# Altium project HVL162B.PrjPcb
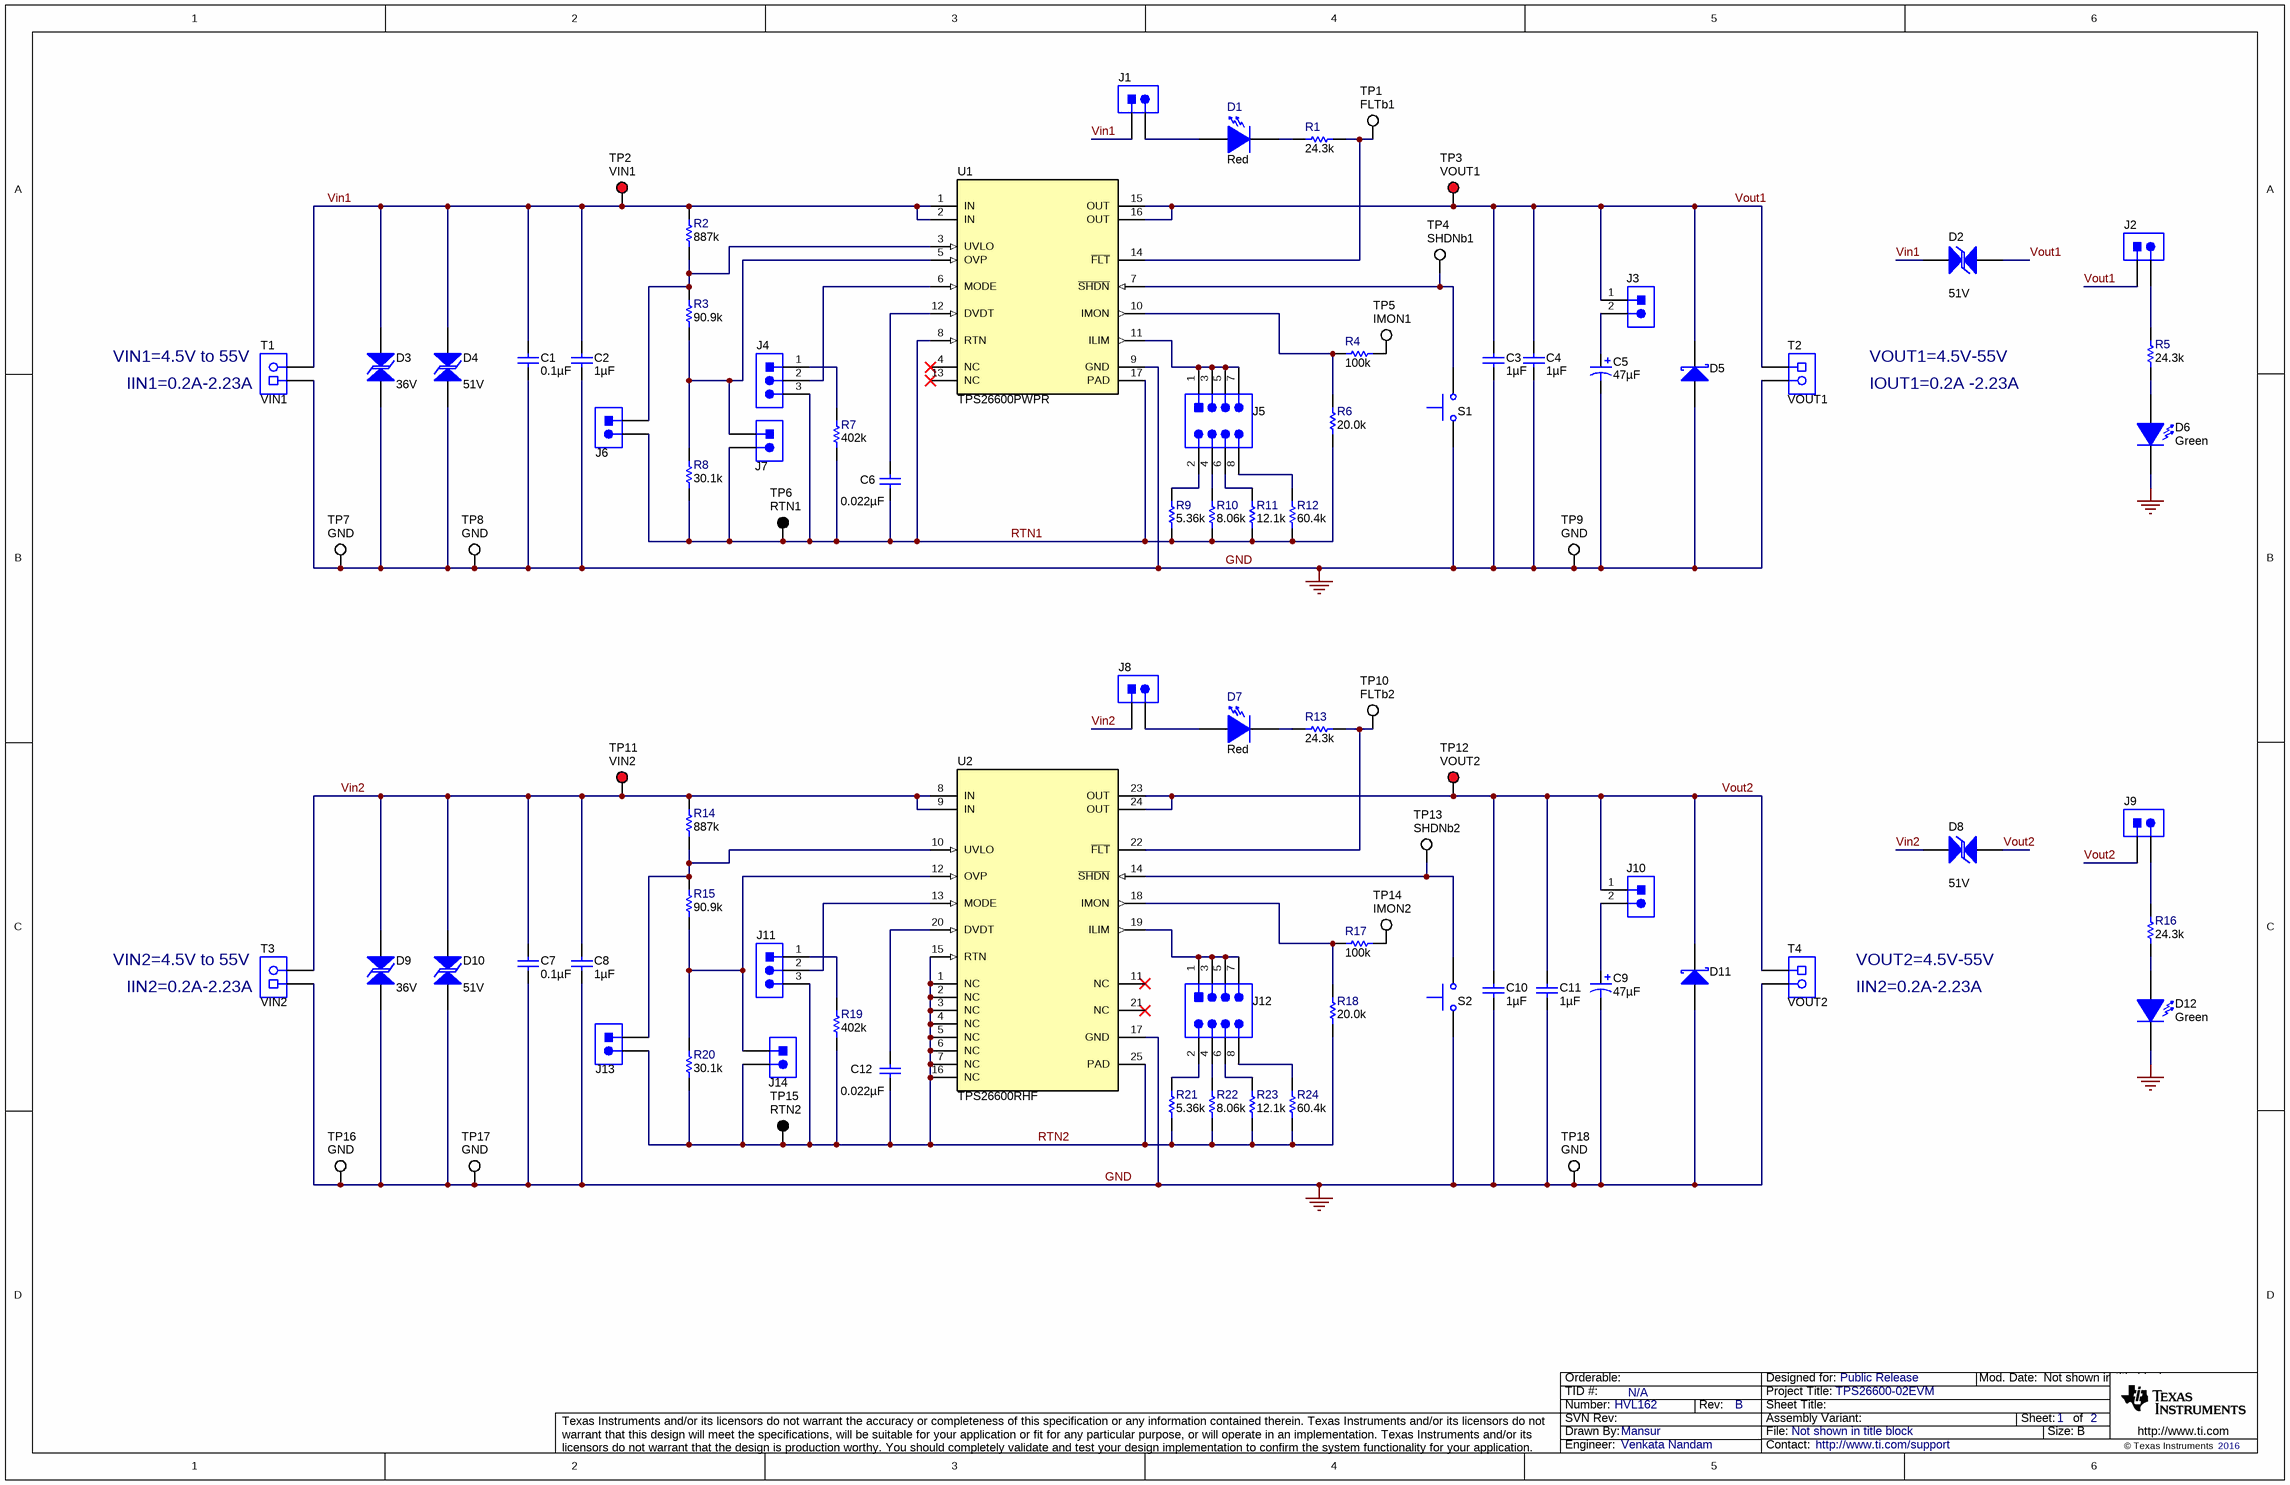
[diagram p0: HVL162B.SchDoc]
TID: N/A; TechSupport: http://www.ti.com/support; SCH_Rev: B; PRJ_Title: TPS26600-02EVM; PRJ_Number: HVL162; PRJ_Engineer: Venkata Nandam; PRJ_Customer: Public Release; PCB_Rev: B; PCB_Layout: Mansur; CopyrightYear: 2016
2 sheets, 116 parts. Net scope: global (net labels, ports and power ports of the same name join across sheets).
Board file: HVL162B.PcbDoc
Sheets:
  HVL162B.SchDoc
  HVL162B_Hardware.SchDoc

## Sheet HVL162B.SchDoc
size 431 x 279 mm; Date: Not shown in title block; ApprovedBy: Not shown in title block; CheckedBy: Not shown in title block; Author: Not shown in title block; CompanyName: Not shown in title block; DrawnBy: Mansur; Engineer: Not shown in title block; Organization: Not shown in title block; Address1: Not shown in title block; Address2: Not shown in title block; Address3: Not shown in title block; Address4: Not shown in title block; DocumentNumber: 1; Revision: Use project parameter SCH_Rev; SheetNumber: 1; SheetTotal: 2; PageSetup: Record=PageOptions¦CenterHorizontal=True¦CenterVertical=True¦PrintScale=0.62¦XCorrection=1.00¦YCorrection=1.00¦PrintKind=0¦BorderSize=5000000¦LeftOffset=0¦BottomOffset=0¦Orientation=2¦PaperLength=1000¦PaperWidth=1000¦Scale=100¦PaperSource=15¦PrintQuality=600¦MediaType=1¦DitherType=10¦PrintScaleMode=1¦PaperKind=Letter

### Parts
C1  ValueDisplayed: 0.1µF  [1206]  (hidden comment: GRM319R72A104KA01D)
C2  ValueDisplayed: 1µF  [1206_180M]  (hidden comment: GRM31CR72A105KA01L)
C3  ValueDisplayed: 1µF  [1206_180M]  (hidden comment: GRM31CR72A105KA01L)
C4  ValueDisplayed: 1µF  [1206_180M]  (hidden comment: GRM31CR72A105KA01L)
C5  ValueDisplayed: 47µF  [SM_RADIAL_G]  (hidden comment: EEETG1J470P)
C6  ValueDisplayed: 0.022µF  [0603]  (hidden comment: GRM188R71C223KA01D)
C7  ValueDisplayed: 0.1µF  [1206]  (hidden comment: GRM319R72A104KA01D)
C8  ValueDisplayed: 1µF  [1206_180M]  (hidden comment: GRM31CR72A105KA01L)
C9  ValueDisplayed: 47µF  [SM_RADIAL_G]  (hidden comment: EEETG1J470P)
C10  ValueDisplayed: 1µF  [1206_180M]  (hidden comment: GRM31CR72A105KA01L)
C11  ValueDisplayed: 1µF  [1206_180M]  (hidden comment: GRM31CR72A105KA01L)
C12  ValueDisplayed: 0.022µF  [0603]  (hidden comment: GRM188R71C223KA01D)
D1  value Red  [LED_LTST-C190_Red]  (hidden comment: LTST-C190CKT)
D2  value 51V  [SMA]  (hidden comment: SMAJ51CA)
D3  value 36V  [SMC]
D4  value 51V  [SMB-Bi]  (hidden comment: SMBJ51CA)
D5  B260A-13-F  [SMA]  (value not drawn)
D6  value Green  [LED_LTST-C190]  (hidden comment: LTST-C190GKT)
D7  value Red  [LED_LTST-C190_Red]  (hidden comment: LTST-C190CKT)
D8  value 51V  [SMA]  (hidden comment: SMAJ51CA)
D9  value 36V  [SMC]
D10  value 51V  [SMB-Bi]  (hidden comment: SMBJ51CA)
D11  B260A-13-F  [SMA]  (value not drawn)
D12  value Green  [LED_LTST-C190]  (hidden comment: LTST-C190GKT)
J1  PBC02SAAN  [Sullins_PBC02SAAN]  (value not drawn)
J2  PBC02SAAN  [Sullins_PBC02SAAN]  (value not drawn)
J3  PBC02SAAN  [Sullins_PBC02SAAN]  (value not drawn)
J4  (no value)  [CONN_PEC03SAAN]
J5  PEC04DAAN  [CONN_PEC04DAAN]  (value not drawn)
J6  PBC02SAAN  [Sullins_PBC02SAAN]  (value not drawn)
J7  PBC02SAAN  [Sullins_PBC02SAAN]  (value not drawn)
J8  PBC02SAAN  [Sullins_PBC02SAAN]  (value not drawn)
J9  PBC02SAAN  [Sullins_PBC02SAAN]  (value not drawn)
J10  PBC02SAAN  [Sullins_PBC02SAAN]  (value not drawn)
J11  (no value)  [CONN_PEC03SAAN]
J12  PEC04DAAN  [CONN_PEC04DAAN]  (value not drawn)
J13  PBC02SAAN  [Sullins_PBC02SAAN]  (value not drawn)
J14  PBC02SAAN  [Sullins_PBC02SAAN]  (value not drawn)
R1  ValueDisplayed: 24.3k  [0603]  (hidden comment: CRCW060324K3FKEA)
R2  ValueDisplayed: 887k  [0603_HV]  (hidden comment: CRCW0603887KFKEA)
R3  ValueDisplayed: 90.9k  [0603_HV]  (hidden comment: CRCW060390K9FKEA)
R4  ValueDisplayed: 100k  [0603]  (hidden comment: CRCW0603100KFKEA)
R5  ValueDisplayed: 24.3k  [0603]  (hidden comment: CRCW060324K3FKEA)
R6  ValueDisplayed: 20.0k  [0603]  (hidden comment: CRCW060320K0FKEA)
R7  ValueDisplayed: 402k  [0603_HV]  (hidden comment: CRCW0603402KFKEA)
R8  ValueDisplayed: 30.1k  [0603_HV]  (hidden comment: CRCW060330K1FKEA)
R9  ValueDisplayed: 5.36k  [0603]  (hidden comment: CRCW06035K36FKEA)
R10  ValueDisplayed: 8.06k  [0603]  (hidden comment: CRCW06038K06FKEA)
R11  ValueDisplayed: 12.1k  [0603]  (hidden comment: CRCW060312K1FKEA)
R12  ValueDisplayed: 60.4k  [0603]  (hidden comment: CRCW060360K4FKEA)
R13  ValueDisplayed: 24.3k  [0603_HV]  (hidden comment: CRCW060324K3FKEA)
R14  ValueDisplayed: 887k  [0603_HV]  (hidden comment: CRCW0603887KFKEA)
R15  ValueDisplayed: 90.9k  [0603_HV]  (hidden comment: CRCW060390K9FKEA)
R16  ValueDisplayed: 24.3k  [0603]  (hidden comment: CRCW060324K3FKEA)
R17  ValueDisplayed: 100k  [0603]  (hidden comment: CRCW0603100KFKEA)
R18  ValueDisplayed: 20.0k  [0603]  (hidden comment: CRCW060320K0FKEA)
R19  ValueDisplayed: 402k  [0603_HV]  (hidden comment: CRCW0603402KFKEA)
R20  ValueDisplayed: 30.1k  [0603_HV]  (hidden comment: CRCW060330K1FKEA)
R21  ValueDisplayed: 5.36k  [0603]  (hidden comment: CRCW06035K36FKEA)
R22  ValueDisplayed: 8.06k  [0603]  (hidden comment: CRCW06038K06FKEA)
R23  ValueDisplayed: 12.1k  [0603]  (hidden comment: CRCW060312K1FKEA)
R24  ValueDisplayed: 60.4k  [0603]  (hidden comment: CRCW060360K4FKEA)
S1  RES-2  [SW_SKRKAEE010]  (value not drawn)
S2  RES-2  [SW_SKRKAEE010]  (value not drawn)
T1  VIN1  [TEC_282841-2]
T2  VOUT1  [TEC_282841-2]
T3  VIN2  [TEC_282841-2]
T4  VOUT2  [TEC_282841-2]
TP1  FLTb1  [Keystone5012]
TP2  VIN1  [Keystone5010]
TP3  VOUT1  [Keystone5010]
TP4  SHDNb1  [Keystone5012]
TP5  IMON1  [Keystone5012]
TP6  RTN1  [Keystone5011]
TP7  GND  [Testpoint_Keystone_Compact]
TP8  GND  [Testpoint_Keystone_Compact]
TP9  GND  [Testpoint_Keystone_Compact]
TP10  FLTb2  [Keystone5012]
TP11  VIN2  [Keystone5010]
TP12  VOUT2  [Keystone5010]
TP13  SHDNb2  [Keystone5012]
TP14  IMON2  [Keystone5012]
TP15  RTN2  [Keystone5011]
TP16  GND  [Testpoint_Keystone_Compact]
TP17  GND  [Testpoint_Keystone_Compact]
TP18  GND  [Testpoint_Keystone_Compact]
U1  PartNumber: TPS26600PWPR  [PWP0016H_N]  (hidden comment: CMP-0074228-2)
U2  TPS26600RHF  [RHF0024A]

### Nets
GND: C1.2 C2.1 C3.2 C4.2 C5.2(-) C7.2 C8.1 C9.2(-) C10.2 C11.2 D3.1 D4.1 D5.2(A) D6.2(K) D9.1 D10.1 D11.2(A) D12.2(K) S1.1 S2.1 T1.1 T2.2 T3.1 T4.2 TP7.1 TP8.1 TP9.1 TP16.1 TP17.1 TP18.1 U1.9(GND) U2.17(GND)
RTN1: C6.2 J4.3 J6.2 J7.2 R6.1 R7.1 R8.1 R9.1 R10.1 R11.1 R12.1 TP6.1 U1.8(RTN) U1.17(PAD)
RTN2: C12.2 J11.3 J13.2 J14.2 R18.1 R19.1 R20.1 R21.1 R22.1 R23.1 R24.1 TP15.1 U2.1(NC) U2.2(NC) U2.3(NC) U2.4(NC) U2.5(NC) U2.6(NC) U2.7(NC) U2.15(RTN) U2.16(NC) U2.25(PAD)
Vin1: C1.1 C2.2 D2.2 D3.2 D4.2 J1.1 R2.2 T1.2 TP2.1 U1.1(IN) U1.2(IN)
Vin2: C7.1 C8.2 D8.2 D9.2 D10.2 J8.1 R14.2 T3.2 TP11.1 U2.8(IN) U2.9(IN)
Vout1: C3.1 C4.1 D2.1 D5.1(K) J2.1 J3.1 T2.1 TP3.1 U1.15(OUT) U1.16(OUT)
Vout2: C10.1 C11.1 D8.1 D11.1(K) J9.1 J10.1 T4.1 TP12.1 U2.23(OUT) U2.24(OUT)
NetC5_1: C5.1(+) J3.2
NetC6_1: C6.1 U1.12(DVDT)
NetC9_1: C9.1(+) J10.2
NetC12_1: C12.1 U2.20(DVDT)
NetD1_1: D1.1(A) J1.2
NetD1_2: D1.2(K) R1.2
NetD6_1: D6.1(A) R5.1
NetD7_1: D7.1(A) J8.2
NetD7_2: D7.2(K) R13.2
NetD12_1: D12.1(A) R16.1
NetJ2_2: J2.2 R5.2
NetJ4_1: J4.1 R7.2
NetJ4_2: J4.2 U1.6(MODE)
NetJ5_1: J5.1 J5.3 J5.5 J5.7 U1.11(ILIM)
NetJ5_2: J5.2 R9.2
NetJ5_4: J5.4 R10.2
NetJ5_6: J5.6 R11.2
NetJ5_8: J5.8 R12.2
NetJ6_1: J6.1 R2.1 R3.2 U1.3(UVLO)
NetJ7_1: J7.1 R3.1 R8.2 U1.5(OVP)
NetJ9_2: J9.2 R16.2
NetJ11_1: J11.1 R19.2
NetJ11_2: J11.2 U2.13(MODE)
NetJ12_1: J12.1 J12.3 J12.5 J12.7 U2.19(ILIM)
NetJ12_2: J12.2 R21.2
NetJ12_4: J12.4 R22.2
NetJ12_6: J12.6 R23.2
NetJ12_8: J12.8 R24.2
NetJ13_1: J13.1 R14.1 R15.2 U2.10(UVLO)
NetJ14_1: J14.1 R15.1 R20.2 U2.12(OVP)
NetR1_1: R1.1 TP1.1 U1.14(~{FLT})
NetR4_1: R4.1 TP5.1
NetR4_2: R4.2 R6.2 U1.10(IMON)
NetR13_1: R13.1 TP10.1 U2.22(~{FLT})
NetR17_1: R17.1 TP14.1
NetR17_2: R17.2 R18.2 U2.18(IMON)
NetS1_2: S1.2 TP4.1 U1.7(~{SHDN})
NetS2_2: S2.2 TP13.1 U2.14(~{SHDN})

Not connected (* = marked no-connect by the designer): U1 4(NC)* 13(NC)*; U2 11(NC)* 21(NC)*

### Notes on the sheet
- (near T1) VIN1=4.5V to 55V
- VOUT1=4.5V-55V
- (near T1) IIN1=0.2A-2.23A
- IOUT1=0.2A -2.23A
- (near T3) VIN2=4.5V to 55V
- VOUT2=4.5V-55V
- (near T3) IIN2=0.2A-2.23A
- IIN2=0.2A-2.23A

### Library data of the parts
C1 C7 = GRM319R72A104KA01D: CAP, CERM, 0.1 µF, 100 V, +/- 10%, X7R, 1206; Manufacturer: MuRata; Polarized: N; CompType: Capacitor; Value: 0.1uF; U/M: EA; Cap_F: 0.0000001; Tolerance_%: 10; Value1: Unknown; VDC_V: 100; Value2: 100V; TaMin_C: -55; TaMax_C: 125; SizeArea_mm2: 5.12; SizeAreaWB_mm2: 10.92; SizeX_mm: 3.2; SizeY_mm: 1.6; SizeZ_mm: 1.35; AEC Category: Q200
C2-C4 C8 C10 C11 = GRM31CR72A105KA01L: CAP, CERM, 1 µF, 100 V, +/- 10%, X7R, 1206; Manufacturer: MuRata; Polarized: N; CompType: Capacitor; Value: 1uF; U/M: EA; Cap_F: 0.000001; Tolerance_%: 10; Value1: Unknown; VDC_V: 100; Value2: 100V; TaMin_C: -55; TaMax_C: 125; Cap_Case: 2220; SizeArea_mm2: 5.12; SizeAreaWB_mm2: 10.92; SizeX_mm: 3.2; SizeY_mm: 1.6; SizeZ_mm: 1.8; AEC Category: Q200
C5 C9 = EEETG1J470P: CAP, AL, 47 µF, 63 V, +/- 20%,  ohm, SMD; Manufacturer: Panasonic; Polarized: Y; CompType: Capacitor; Value: 47uF; U/M: EA; Cap_F: 0.000047; Tolerance_%: 20; Value1: Unknown; VDC_V: 63; Value2: 63V; IRMS_A: 0.15; TaMin_C: -40; TaMax_C: 125; Cap_Case: 10x10.2mm
C6 C12 = GRM188R71C223KA01D: CAP, CERM, 0.022 µF, 16 V, +/- 10%, X7R, 0603; Manufacturer: MuRata; Polarized: N; CompType: Capacitor; Value: 0.022uF; U/M: EA; Cap_F: 0.000000022; Tolerance_%: 10; Value1: Unknown; VDC_V: 16; Value2: 16V; TaMin_C: -55; TaMax_C: 125; SizeArea_mm2: 1.28; SizeAreaWB_mm2: 4.68; SizeX_mm: 1.6; SizeY_mm: 0.8; SizeZ_mm: 1; AEC Category: Q200
D1 D7 = LTST-C190CKT: LED, Red, SMD; Manufacturer: Lite-On; Vf_V: 2; Value2: 2V; Io_A: 0.02; Tjmax_C: 85; Power_TotalModule: 0.0625; Value1: 0.0625W; U/M: EA
D2 D8 = SMAJ51CA: Diode, TVS, Bi, 51 V, 400 W, SMA; Manufacturer: Littelfuse; U/M: EA; Power_W: 400; Vr_V: 51; Value1: 400W; RJA_CperW: 120; AEC Category: Q101; SizeAreaWB_mm2: 37.3428; SizeArea_mm2: 16.3228; SizeX_mm: 5.59; SizeY_mm: 2.92; SizeZ_mm: 2.87
D3 D9 = SMCJ33CA: TVS DIODE 36VWM 58.1VC SMC; PartNumber: SMCJ36CA; Manufacturer: Bourns; U/M: EA; Power_W: 1500; Vr_V: 33; Value1: 1500W; AEC Category: Q101
D4 D10 = SMBJ51CA: Diode, TVS, Bi, 51 V, 600 W, SMB; Manufacturer: Bourns; U/M: EA; Power_W: 600; Vr_V: 51; Value1: 600W; AEC Category: Q101; AEC Qualified: N
D5 D11 = B260A-13-F: Diode, Schottky, 60 V, 2 A, SMA; Manufacturer: Diodes Inc.; Value: 60V; U/M: EA; Vf_V: 0.7; Io_A: 2; Value1: 2A; Vr_V: 60; Value2: 0.7V; TJmax_C: 150; RJC_CperW: 20; AEC Category: Q101; SizeAreaWB_mm2: 37.3428; SizeArea_mm2: 16.3228; SizeX_mm: 5.59; SizeY_mm: 2.92; SizeZ_mm: 2.87
D6 D12 = LTST-C190GKT: LED, Green, SMD; Manufacturer: Lite-On; Vf_V: 2.1; Value2: 2.1V; Io_A: 0.02; Power_TotalModule: 0.1; Value1: 0.1W; U/M: EA
J1 J6-J8 J13 J14 = PBC02SAAN: Header, 100mil, 2x1, Gold, TH; Manufacturer: Sullins Connector Solutions; SymbolCreator: a0412235; Pitch_mm: 2.54; Gender: Male; Shrouded: N; Row_Count: 1; Current_A: 3; Voltage_V: 1800; Cert_UL: Y
J2 J3 J9 J10 = PBC02SAAN: Header, 100mil, 2x1, Gold, TH; Manufacturer: Sullins Connector Solutions; U/M: EA; SymbolCreator: a0412235
J4 J11 = PEC03SAAN: Header, 100mil, 3x1, Tin, TH; Manufacturer: Sullins Connector Solutions; U/M: EA; SymbolCreator: a0799628
J5 J12 = PEC04DAAN: Header, 100mil, 4x2, Tin, TH; Manufacturer: Sullins Connector Solutions; U/M: EA; SymbolCreator: a0411947
R1 R13 = CRCW060324K3FKEA: RES, 24.3 k, 1%, 0.1 W, 0603; Manufacturer: Vishay-Dale; CompType: Resistor; Value: 24.3k; Res_ohm: 24300; Value_Code: 24k3; Tolerance_%: 1; Power_W: 0.1; Value2: 0.1W; VDC_V: 75; TempCo: 100 ppm/C; EIA_Code: E96; U/M: EA
R2 R14 = CRCW0603887KFKEA: RES, 887 k, 1%, 0.1 W, 0603; Manufacturer: Vishay-Dale; CompType: Resistor; Value: 887k; Res_ohm: 887000; Tolerance_%: 1; Power_W: 0.1; Value2: 0.1W; VDC_V: 75; TempCo: 100 ppm/C; EIA_Code: E96; U/M: EA
R3 R15 = CRCW060390K9FKEA: RES, 90.9 k, 1%, 0.1 W, 0603; Manufacturer: Vishay-Dale; CompType: Resistor; Value: 90.9k; Res_ohm: 90900; Value_Code: 90k9; Tolerance_%: 1; Power_W: 0.1; Value2: 0.1W; VDC_V: 75; TempCo: 100 ppm/C; EIA_Code: E96; U/M: EA
R4 R17 = CRCW0603100KFKEA: RES, 100 k, 1%, 0.1 W, 0603; Manufacturer: Vishay-Dale; CompType: Resistor; Value: 100k; Res_ohm: 100000; Tolerance_%: 1; Power_W: 0.1; Value2: 0.1W; VDC_V: 75; TempCo: 100 ppm/C; EIA_Code: E96; U/M: EA; SizeArea_mm2: 1.28; SizeX_mm: 1.6; SizeY_mm: 0.8; AEC Category: Q200
R5 R16 = CRCW060324K3FKEA: RES, 24.3 k, 1%, 0.1 W, 0603; Manufacturer: Vishay-Dale; CompType: Resistor; Value: 24.3k; Res_ohm: 24300; Value_Code: 24k3; Tolerance_%: 1; Power_W: 0.1; Value2: 0.1W; VDC_V: 75; TempCo: 100 ppm/C; EIA_Code: E96; U/M: EA; SizeArea_mm2: 1.28; SizeX_mm: 1.6; SizeY_mm: 0.8; AEC Category: Q200
R6 R18 = CRCW060320K0FKEA: RES, 20.0 k, 1%, 0.1 W, 0603; Manufacturer: Vishay-Dale; CompType: Resistor; Value: 20.0k; Res_ohm: 20000; Value_Code: 20k0; Tolerance_%: 1; Power_W: 0.1; Value2: 0.1W; VDC_V: 75; TempCo: 100 ppm/C; EIA_Code: E96; U/M: EA
R7 R19 = CRCW0603402KFKEA: RES, 402 k, 1%, 0.1 W, 0603; Manufacturer: Vishay-Dale; CompType: Resistor; Value: 402k; Res_ohm: 402000; Tolerance_%: 1; Power_W: 0.1; Value2: 0.1W; VDC_V: 75; TempCo: 100 ppm/C; EIA_Code: E96; U/M: EA
R8 R20 = CRCW060330K1FKEA: RES, 30.1 k, 1%, 0.1 W, 0603; Manufacturer: Vishay-Dale; CompType: Resistor; Value: 30.1k; Res_ohm: 30100; Value_Code: 30k1; Tolerance_%: 1; Power_W: 0.1; Value2: 0.1W; VDC_V: 75; TempCo: 100 ppm/C; EIA_Code: E96; U/M: EA
R9 R21 = CRCW06035K36FKEA: RES, 5.36 k, 1%, 0.1 W, 0603; Manufacturer: Vishay-Dale; CompType: Resistor; Value: 5.36k; Res_ohm: 5360; Value_Code: 5k36; Tolerance_%: 1; Power_W: 0.1; Value2: 0.1W; VDC_V: 75; TempCo: 100 ppm/C; EIA_Code: E96; U/M: EA; SizeArea_mm2: 1.28; SizeX_mm: 1.6; SizeY_mm: 0.8; AEC Category: Q200
R10 R22 = CRCW06038K06FKEA: RES, 8.06 k, 1%, 0.1 W, 0603; Manufacturer: Vishay-Dale; CompType: Resistor; Value: 8.06k; Res_ohm: 8060; Value_Code: 8k06; Tolerance_%: 1; Power_W: 0.1; Value2: 0.1W; VDC_V: 75; TempCo: 100 ppm/C; EIA_Code: E96; U/M: EA; SizeArea_mm2: 1.28; SizeX_mm: 1.6; SizeY_mm: 0.8; AEC Category: Q200
R11 R23 = CRCW060312K1FKEA: RES, 12.1 k, 1%, 0.1 W, 0603; Manufacturer: Vishay-Dale; CompType: Resistor; Value: 12.1k; Res_ohm: 12100; Value_Code: 12k1; Tolerance_%: 1; Power_W: 0.1; Value2: 0.1W; VDC_V: 75; TempCo: 100 ppm/C; EIA_Code: E96; U/M: EA; SizeArea_mm2: 1.28; SizeX_mm: 1.6; SizeY_mm: 0.8; AEC Category: Q200
R12 R24 = CRCW060360K4FKEA: RES, 60.4 k, 1%, 0.1 W, 0603; Manufacturer: Vishay-Dale; CompType: Resistor; Value: 60.4k; Res_ohm: 60400; Value_Code: 60k4; Tolerance_%: 1; Power_W: 0.1; Value2: 0.1W; VDC_V: 75; TempCo: 100 ppm/C; EIA_Code: E96; U/M: EA; SizeArea_mm2: 1.28; SizeX_mm: 1.6; SizeY_mm: 0.8; AEC Category: Q200
S1 S2 = SKRKAEE010: Switch, Push Button, SMD; Manufacturer: Alps; Alternate Manufacturer: Any; Alternate PartNumber: Equivalent; SymbolCreator: a0412235; Circuit: SPST-NO; VDC_V: 12; SwitchFunction: Off-Mom; PositionCount: 1; CurrentRating_mA: 50
T1-T4 = 282841-2: Terminal Block, 2x1, 5.08mm, TH; Manufacturer: TE Connectivity; SymbolCreator: a0412235; U/M: EA
TP1 TP4 TP5 TP10 TP13 TP14 = 5012: Test Point, TH, Multipurpose, White; Manufacturer: Keystone; Alternate Manufacturer: Any; Alternate PartNumber: Equivalent; CompType: Test Point Loop; U/M: EA
TP2 TP3 TP11 TP12 = 5010: Test Point, Multipurpose, Red, TH; Manufacturer: Keystone; CompType: Test Point Loop; U/M: EA
TP6 TP15 = 5011: Test Point, Multipurpose, Black, TH; Manufacturer: Keystone; CompType: Test Point Loop; U/M: EA
TP7-TP9 TP16-TP18 = 5016: Test Point, SMT, Compact; Manufacturer: Keystone; Alternate Manufacturer: Any; Alternate PartNumber: Equivalent; CompType: Test Point Loop; U/M: EA
U1 = CMP-0074228-2: 60V 2A Industrial eFuse With Integrated Reverse-Input Polarity Protection, PWP0016H (TSSOP-16); Alternate PartNumber: TPS26600PWPT; Manufacturer: Texas Instruments; CompType: IC; U/M: EA; SizeArea_mm2: 32.0; SizeAreaWB_mm2: 58.8; SizeX_mm: 6.4; SizeY_mm: 5.0; SizeZ_mm: 1.2
U2 = CMP-0013838-2: 4.5V - 55V, 2A Industrial eFuse with Integrated Reverse Input Polarity Protection, RHF0024A (VQFN-24); Manufacturer: Texas Instruments; SizeX_mm: 4; SizeY_mm: 5; CompType: IC; SizeZ_mm: 1; SizeArea_mm2: 20; SizeAreaWB_mm2: 42; U/M: EA

## Sheet HVL162B_Hardware.SchDoc
size 431 x 279 mm; Date: Not shown in title block; ApprovedBy: Not shown in title block; CheckedBy: Not shown in title block; Author: Not shown in title block; CompanyName: Not shown in title block; DrawnBy: Mansur; Engineer: Not shown in title block; Organization: Not shown in title block; Address1: Not shown in title block; Address2: Not shown in title block; Address3: Not shown in title block; Address4: Not shown in title block; DocumentNumber: 1; Revision: Use project parameter SCH_Rev; SheetNumber: 2; SheetTotal: 2; PageSetup: Record=PageOptions¦CenterHorizontal=True¦CenterVertical=True¦PrintScale=1.00¦XCorrection=1.00¦YCorrection=1.00¦PrintKind=0¦BorderSize=5000000¦LeftOffset=0¦BottomOffset=0¦Orientation=2¦PaperLength=1000¦PaperWidth=1000¦Scale=100¦PaperSource=15¦PrintQuality=600¦MediaType=1¦DitherType=10¦PaperKind=Letter¦PrintScaleMode=1
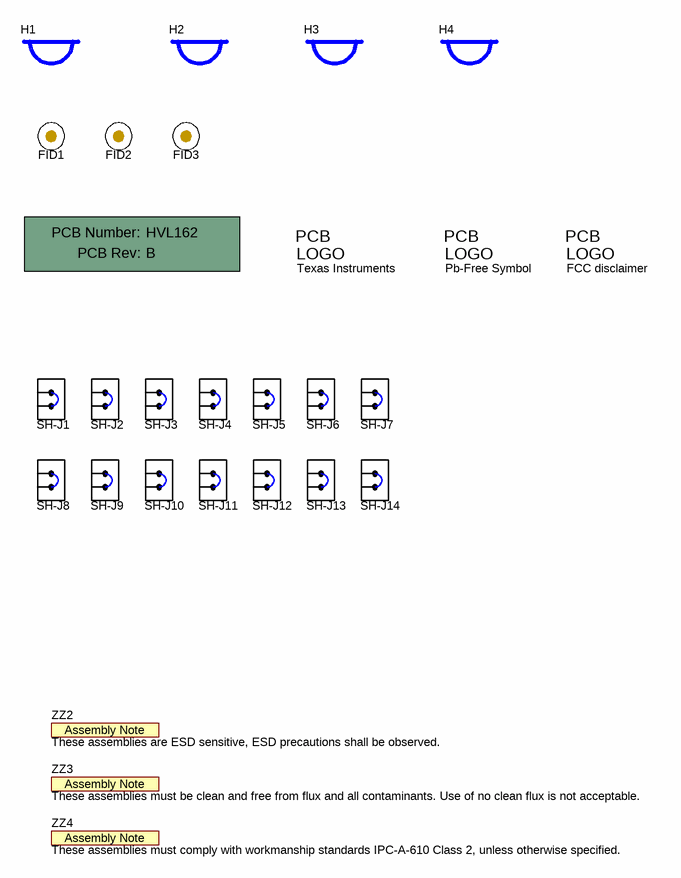
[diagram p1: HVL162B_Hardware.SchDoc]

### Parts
!PCB1  Printed Circuit Board  (value not drawn)  (mechanical)
FID1  Fiducial  [Fiducial10-20]  (value not drawn)
FID2  Fiducial  [Fiducial10-20]  (value not drawn)
FID3  Fiducial  [Fiducial10-20]  (value not drawn)
H1  (no value)  [Bumpon_SJ5003Transparent]
H2  (no value)  [Bumpon_SJ5003Transparent]
H3  (no value)  [Bumpon_SJ5003Transparent]
H4  (no value)  [Bumpon_SJ5003Transparent]
Logo1  Texas Instruments  [TI_Stacked_Overlay_Small]  (no BOM)
Logo2  Pb-Free Symbol  [Pb-Free_Overlay_Small]  (no BOM)
Logo3  FCC disclaimer  [FCC_disclaimer]  (no BOM)
SH-J1  SPC02SYAN  [SPC02SYAN]  (value not drawn)
SH-J2  SPC02SYAN  [SPC02SYAN]  (value not drawn)
SH-J3  SPC02SYAN  [SPC02SYAN]  (value not drawn)
SH-J4  SPC02SYAN  [SPC02SYAN]  (value not drawn)
SH-J5  SPC02SYAN  [SPC02SYAN]  (value not drawn)
SH-J6  SPC02SYAN  [SPC02SYAN]  (value not drawn)
SH-J7  SPC02SYAN  [SPC02SYAN]  (value not drawn)
SH-J8  SPC02SYAN  [SPC02SYAN]  (value not drawn)
SH-J9  SPC02SYAN  [SPC02SYAN]  (value not drawn)
SH-J10  SPC02SYAN  [SPC02SYAN]  (value not drawn)
SH-J11  SPC02SYAN  [SPC02SYAN]  (value not drawn)
SH-J12  SPC02SYAN  [SPC02SYAN]  (value not drawn)
SH-J13  SPC02SYAN  [SPC02SYAN]  (value not drawn)
SH-J14  SPC02SYAN  [SPC02SYAN]  (value not drawn)
ZZ2  These assemblies are ESD sensitive, ESD precautions shall be observed.  [AssemblyNote]  (no BOM)
ZZ3  These assemblies must be clean and free from flux and all contaminants. Use of no clean flux is not acceptable.  [AssemblyNote]  (no BOM)
ZZ4  These assemblies must comply with workmanship standards IPC-A-610 Class 2, unless otherwise specified.  [AssemblyNote]  (no BOM)

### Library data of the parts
!PCB1 = PCB: Manufacturer: Any; PartNumber: HVL162; SymbolCreator: a0412235
FID1-FID3 = Fiducial: Fiducial mark.  There is nothing to buy or mount.; SymbolCreator: codlsc
H1-H4 = SJ-5303 (CLEAR): Bumpon, Hemisphere, 0.44 X 0.20, Clear; Manufacturer: 3M; SymbolCreator: a0412235
Logo1 = TI_Logo: Texas Instrument Corporate Signature; SymbolCreator: codlsc
Logo2 = Pb-Free: SymbolCreator: a0412235
Logo3 = FCC_disclaimer: SymbolCreator: codlsc
SH-J1-SH-J14 = SPC02SYAN: Shunt, 100mil, Flash Gold, Black; Manufacturer: Sullins Connector Solutions; Value: 1x2; Note: You can "mate" this to a header by matching the designator.  i.e. use SH-J3 for header J3
ZZ2-ZZ4 = AssemblyNote: SymbolCreator: codlsc

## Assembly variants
001: not fitted C1 C4 C7 C11 D2 D3 D8 D9 FID1 FID2 FID3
